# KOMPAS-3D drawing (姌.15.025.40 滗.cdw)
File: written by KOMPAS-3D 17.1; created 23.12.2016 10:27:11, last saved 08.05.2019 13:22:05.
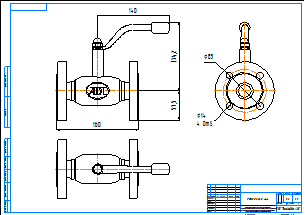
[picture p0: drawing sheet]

Sheet 1: A2, landscape

Title block, sheet 1: name: КШ.15.025.40 фф; material: Внимание! Данный продукт является объектом авторского права ООО «Торговый Дом АДЛ». / Запрещается изменение, копирование, распространение / (в том числе путем копирования на другие сайты и ресурсы в Интернете) / или любое иное использование информации и объектов без предварительного / согласия правообладателя (ООО «Торговый Дом АДЛ»).; mass: 1,3; sheets: 1; organisation: ООО "Торговый дом АДЛ"; sheet format: A2; stored path: C:\Users\tra\Desktop\2д чертежи\Шаровые краны БИВАЛ\КШ_Бивал_серия_14_15\KOMPAS_2D\КШ.15.025.40 фф.cdw

Views: Вид 1, Проекционный вид 2, Проекционный вид 3
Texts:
  Klimkovich
  ADL
Dimensions and other numbers on the sheet: 160; 140; 134,2; 57,5; 85; 14; 4 Отв.; 1:1; 1; 1,3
